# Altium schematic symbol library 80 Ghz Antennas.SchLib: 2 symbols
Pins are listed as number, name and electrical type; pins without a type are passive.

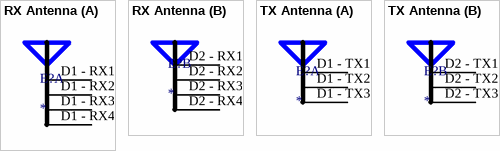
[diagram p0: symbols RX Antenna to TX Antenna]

## RX Antenna
designator E?
footprint RX Antenna (RX 80 Ghz Antenna)
part A pins: D1 - RX1, D1 - RX2, D1 - RX3, D1 - RX4
part B pins: D2 - RX1, D2 - RX2, D2 - RX3, D2 - RX4

## TX Antenna
designator E?
footprint TX Antenna (TX 80 Ghz Antenna)
part A pins: D1 - TX1, D1 - TX2, D1 - TX3
part B pins: D2 - TX1, D2 - TX2, D2 - TX3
